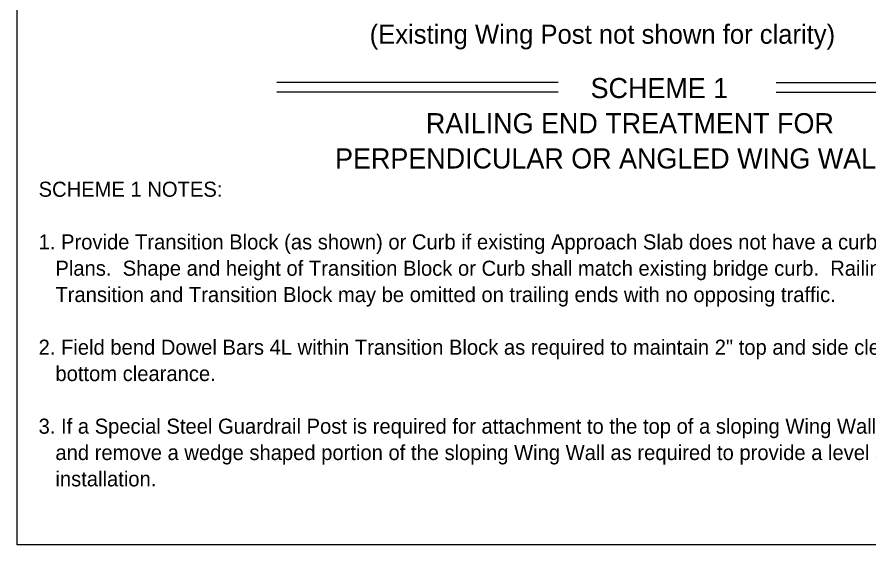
# Model space of a CAD drawing. Extents: x 1.5 to 68.7, y 0 to 31.
# Drawn here: x 1.47 to 12.85, y 1.78 to 8.84 of the extents above; entities that cross this region are included whole.
import ezdxf

# ---------------------------------------------------------------- set-up
doc = ezdxf.new("R2010")
doc.units = 0
doc.layers.add('ActivePts-ConstElements', color=7, linetype='Continuous')
doc.layers.add('AdhocPoint_dp', color=7, linetype='Continuous')

msp = doc.modelspace()

# ---------------------------------------------------------------- linework, layer by layer
at = {"layer": 'ActivePts-ConstElements'}
msp.add_lwpolyline([(1.467, 28.183), (42.533, 28.183), (42.533, 1.783), (1.467, 1.783)], close=True, dxfattribs=at)
at = {"layer": 'AdhocPoint_dp'}
for p, q in [((8.699, 7.968), (4.94, 7.968)), ((11.614, 7.968), (15.974, 7.968)), ((8.699, 7.835), (4.94, 7.835)), ((11.614, 7.835), (15.974, 7.835))]:
    msp.add_line(p, q, dxfattribs=at)

# ---------------------------------------------------------------- texts
for s, height, p in [('(Existing Wing Post not shown for clarity)', 0.256, (6.179, 8.484)), ('SCHEME 1', 0.2688, (9.132, 7.757)), ('RAILING END TREATMENT FOR ', 0.2688, (6.931, 7.287)), ('PERPENDICULAR OR ANGLED WING WALLS', 0.2688, (5.717, 6.816)), ('SCHEME 1 NOTES:', 0.2016, (1.755, 6.438)), ('1. Provide Transition Block (as shown) or Curb if existing Approach Slab does not have a curb, see Roadway ', 0.2016, (1.755, 5.734)), ('   Plans.  Shape and height of Transition Block or Curb shall match existing bridge curb.  Railing End ', 0.2016, (1.755, 5.382)), ('   Transition and Transition Block may be omitted on trailing ends with no opposing traffic.', 0.2016, (1.755, 5.03)), ('2. Field bend Dowel Bars 4L within Transition Block as required to maintain 2" top and side clearance and 3" ', 0.2016, (1.755, 4.326)), ('   bottom clearance.   ', 0.2016, (1.755, 3.974)), ('3. If a Special Steel Guardrail Post is required for attachment to the top of a sloping Wing Wall, saw cut ', 0.2016, (1.755, 3.27)), ('   and remove a wedge shaped portion of the sloping Wing Wall as required to provide a level surface for post', 0.2016, (1.755, 2.918)), ('   installation.', 0.2016, (1.755, 2.566))]:
    msp.add_text(s, height=height, dxfattribs=at).set_placement(p)

doc.saveas('drawing.dxf')
